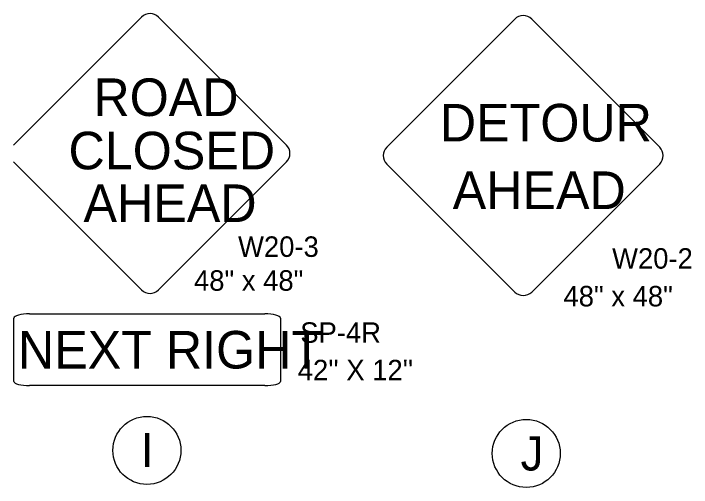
# Model space of a CAD drawing. Extents: x 2157572 to 5059327, y 715220 to 1674494.
# Drawn here: x 2164515 to 2165480, y 720781 to 721456 of the extents above; entities that cross this region are included whole.
import ezdxf

# ---------------------------------------------------------------- set-up
doc = ezdxf.new("R2010")
doc.units = 0
for name, color, linetype in [('Exist Civil Demographics City or Town Circle Label', 7, 'Continuous'), ('Exist Cultural Church Label', 7, 'Continuous'), ('Exist Road Secondary Type 20 SR Number Label', 7, 'Continuous'), ('Map Preparation County Base Legend Highway Garage or Maintenance Office', 7, 'Continuous')]:
    doc.layers.add(name, color=color, linetype=linetype)

msp = doc.modelspace()

# ---------------------------------------------------------------- linework, layer by layer
at = {"layer": 'Exist Civil Demographics City or Town Circle Label'}
for points in [[(2165046.51, 721265.29), (2165228.77, 721447.55)], [(2165252.84, 721447.55), (2165435.1, 721265.3)], [(2165228.77, 721058.96), (2165046.51, 721241.22)], [(2165435.1, 721241.22), (2165252.84, 721058.96)]]:
    msp.add_lwpolyline(points, dxfattribs=at)
for centre, start, end in [((2165240.8, 721435.51), 44.98697, 135), ((2165058.55, 721253.25), 135, 225), ((2165423.07, 721253.25), 315, 45), ((2165240.81, 721071), 225, 315)]:
    msp.add_arc(centre, 17.02, start, end, dxfattribs=at)
at = {"layer": 'Exist Cultural Church Label'}
for centre in [(2164704.96, 720833.37), (2165245.11, 720829.07)]:
    msp.add_circle(centre, 48.43, dxfattribs=at)
at = {"layer": 'Exist Road Secondary Type 20 SR Number Label'}
msp.add_line((2164537.77, 721027.81), (2164872.85, 721027.81), dxfattribs=at)
for points in [[(2164515.1, 721268.26), (2164697.37, 721450.52)], [(2164721.44, 721450.51), (2164903.7, 721268.26)], [(2164697.37, 721061.93), (2164515.1, 721244.18)], [(2164903.7, 721244.18), (2164721.44, 721061.93)], [(2164515.64, 720931.64), (2164515.64, 721021.86)], [(2164894.97, 721021.85), (2164894.97, 720931.64)], [(2164872.85, 720925.69), (2164537.77, 720925.68)]]:
    msp.add_lwpolyline(points, dxfattribs=at)
for centre, start, end in [((2164709.4, 721438.48), 44.98697, 135), ((2164891.66, 721256.22), 315, 45), ((2164709.4, 721073.96), 225, 315)]:
    msp.add_arc(centre, 17.02, start, end, dxfattribs=at)
for centre, major_axis, start_param, end_param in [((2164537.77, 721021.85), (-22.13, 0), 4.712162, 6.283185), ((2164872.85, 721021.85), (22.13, 0), 0, 1.570796), ((2164537.77, 720931.64), (-22.13, 0), 0, 1.570796), ((2164872.85, 720931.64), (-22.13, 0), 1.570796, 3.141593)]:
    msp.add_ellipse(centre, major_axis=major_axis, ratio=0.269231, start_param=start_param, end_param=end_param, dxfattribs=at)
at = {"layer": 'Map Preparation County Base Legend Highway Garage or Maintenance Office'}
for centre in [(2164704.96, 720833.37), (2165245.11, 720829.07)]:
    msp.add_circle(centre, 48.43, dxfattribs=at)

# ---------------------------------------------------------------- texts
at = {"layer": 'Exist Civil Demographics City or Town Circle Label'}
for s, height, p in [('DETOUR', 53.496, (2165122.08, 721273.33)), ('AHEAD', 53.496, (2165140.37, 721177.18)), ('W20-2', 29.18, (2165367.37, 721092.19)), ('48" x 48"', 29.18, (2165298.15, 721038.45))]:
    msp.add_text(s, height=height, dxfattribs=at).set_placement(p)
at = {"layer": 'Exist Cultural Church Label'}
for s, p in [('I', (2164696.13, 720809.71)), ('J', (2165237.11, 720804.76))]:
    msp.add_text(s, height=48.63, dxfattribs=at).set_placement(p)
at = {"layer": 'Exist Road Secondary Type 20 SR Number Label'}
for s, height, p in [('ROAD', 53.496, (2164628.77, 721309.62)), ('CLOSED', 53.496, (2164593.31, 721233.68)), ('AHEAD', 53.496, (2164614.71, 721158.68)), ('W20-3', 29.18, (2164834.79, 721108.97)), ('48" x 48"', 29.18, (2164772.04, 721060.78)), ('SP-4R', 29.18, (2164923.31, 720986.59)), ('NEXT RIGHT', 53.496, (2164521.29, 720950)), ("42'' X 12''", 29.1797, (2164919.78, 720933.22))]:
    msp.add_text(s, height=height, dxfattribs=at).set_placement(p)

doc.saveas('drawing.dxf')
